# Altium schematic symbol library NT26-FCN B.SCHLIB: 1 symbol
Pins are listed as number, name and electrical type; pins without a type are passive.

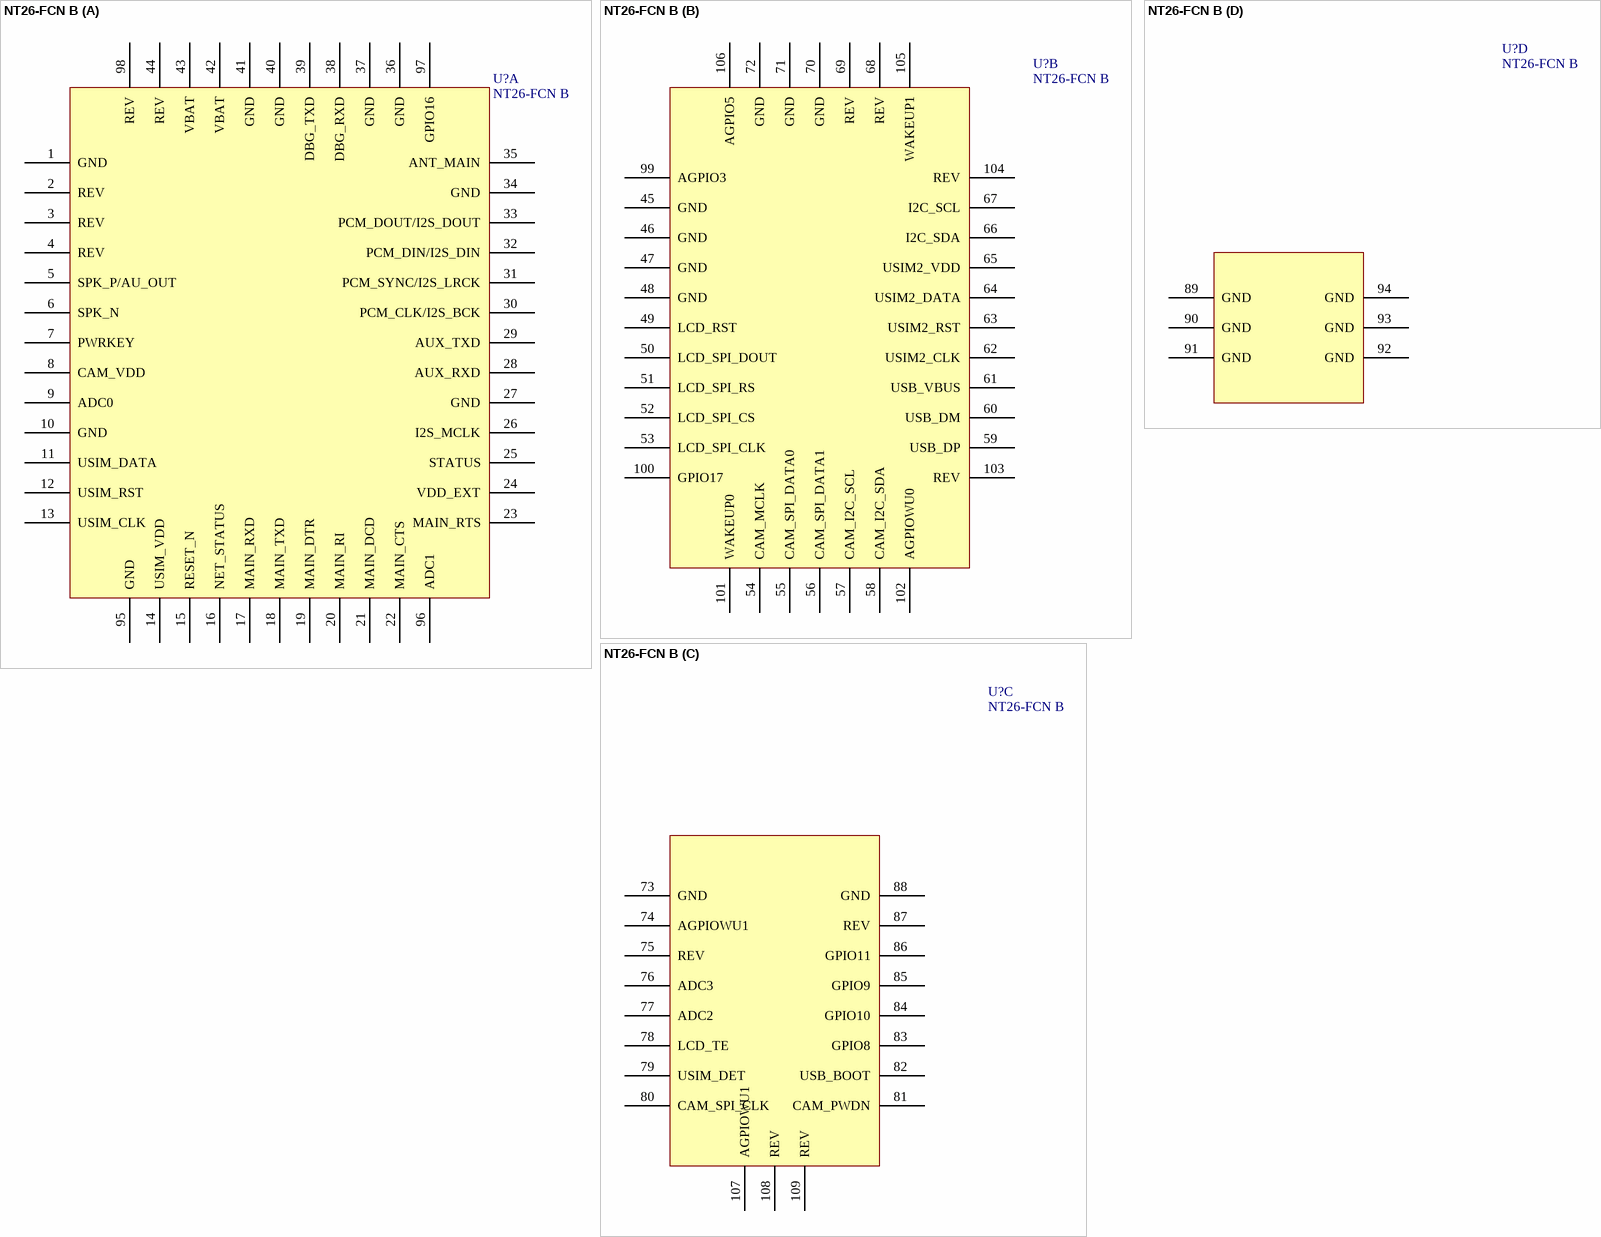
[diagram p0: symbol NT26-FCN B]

## NT26-FCN B
designator U?
footprint NT26-FCN B (Footprint not found)
part A pins: 1 GND, 2 REV, 3 REV, 4 REV, 5 SPK_P/AU_OUT, 6 SPK_N, 7 PWRKEY, 8 CAM_VDD, 9 ADC0, 10 GND, 11 USIM_DATA, 12 USIM_RST, 13 USIM_CLK, 14 USIM_VDD, 15 RESET_N, 16 NET_STATUS, 17 MAIN_RXD, 18 MAIN_TXD, 19 MAIN_DTR, 20 MAIN_RI, 21 MAIN_DCD, 22 MAIN_CTS, 23 MAIN_RTS, 24 VDD_EXT, 25 STATUS, 26 I2S_MCLK, 27 GND, 28 AUX_RXD, 29 AUX_TXD, 30 PCM_CLK/I2S_BCK, 31 PCM_SYNC/I2S_LRCK, 32 PCM_DIN/I2S_DIN, 33 PCM_DOUT/I2S_DOUT, 34 GND, 35 ANT_MAIN, 36 GND, 37 GND, 38 DBG_RXD, 39 DBG_TXD, 40 GND, 41 GND, 42 VBAT, 43 VBAT, 44 REV, 95 GND, 96 ADC1, 97 GPIO16, 98 REV
part B pins: 45 GND, 46 GND, 47 GND, 48 GND, 49 LCD_RST, 50 LCD_SPI_DOUT, 51 LCD_SPI_RS, 52 LCD_SPI_CS, 53 LCD_SPI_CLK, 54 CAM_MCLK, 55 CAM_SPI_DATA0, 56 CAM_SPI_DATA1, 57 CAM_I2C_SCL, 58 CAM_I2C_SDA, 59 USB_DP, 60 USB_DM, 61 USB_VBUS, 62 USIM2_CLK, 63 USIM2_RST, 64 USIM2_DATA, 65 USIM2_VDD, 66 I2C_SDA, 67 I2C_SCL, 68 REV, 69 REV, 70 GND, 71 GND, 72 GND, 99 AGPIO3, 100 GPIO17, 101 WAKEUP0, 102 AGPIOWU0, 103 REV, 104 REV, 105 WAKEUP1, 106 AGPIO5
part C pins: 73 GND, 74 AGPIOWU1, 75 REV, 76 ADC3, 77 ADC2, 78 LCD_TE, 79 USIM_DET, 80 CAM_SPI_CLK, 81 CAM_PWDN, 82 USB_BOOT, 83 GPIO8, 84 GPIO10, 85 GPIO9, 86 GPIO11, 87 REV, 88 GND, 107 AGPIOWU1, 108 REV, 109 REV
part D pins: 89 GND, 90 GND, 91 GND, 92 GND, 93 GND, 94 GND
